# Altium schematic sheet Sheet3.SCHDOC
size B
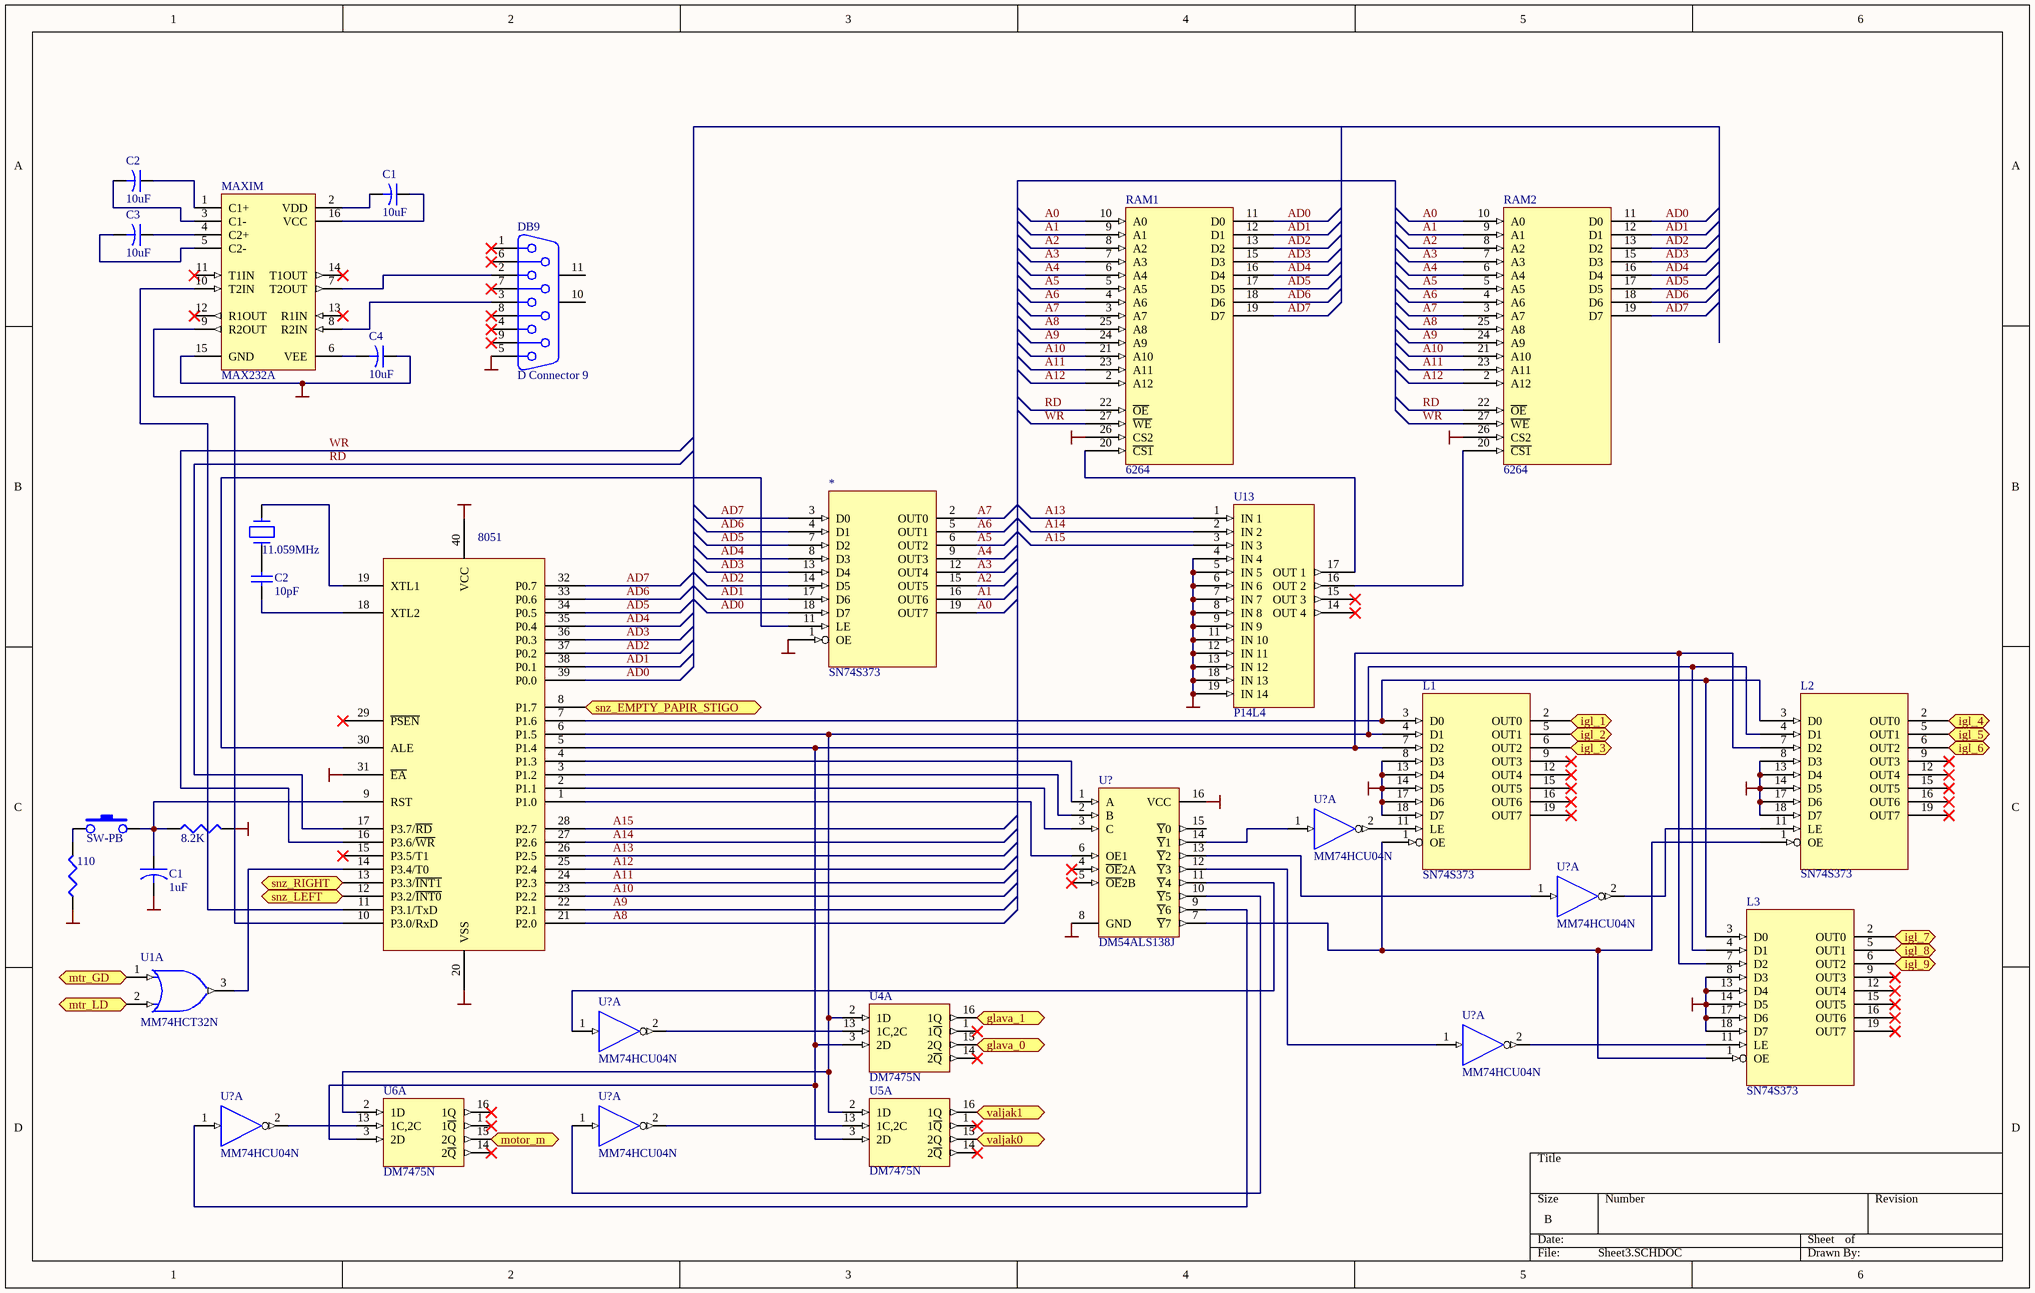
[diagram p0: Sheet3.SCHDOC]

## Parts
(Parts that share a designator on the sheet are numbered #1, #2 ... from top to bottom, then left to right.)
*  SN74S373
?#1  8051
?#2  11.059MHz
?#3  SW-PB
?#4  8.2K
?#5  110
C1#1  10uF  [CAPR5-4X5]
C1#2  1uF
C2#1  10uF  [CAPR5-4X5]
C2#2  value 10pF  [C3216-1206]
C3  10uF  [CAPR5-4X5]
C4  10uF  [CAPR5-4X5]
DB9  D Connector 9  [DSUB1.385-2H9]
L1  SN74S373
L2  SN74S373
L3  SN74S373
MAXIM  MAX232A  [SO-G16/G6.9]
RAM1  6264  [DIP28]
RAM2  6264  [DIP28]
U1  MM74HCT32N  [DIP-14/D19.7]  (part A of 4)
U4  DM7475N  [DIP-16]  (part A of 2)
U5  DM7475N  [DIP-16]  (part A of 2)
U6  DM7475N  [DIP-16]  (part A of 2)
U13  P14L4  [DIP20]
U?#1  DM54ALS138J  [DIP-16]
U?#2  MM74HCU04N  [DIP-14/D19.7]  (part A of 6)
U?#3  MM74HCU04N  [DIP-14/D19.7]  (part A of 6)
U?#4  MM74HCU04N  [DIP-14/D19.7]  (part A of 6)
U?#5  MM74HCU04N  [DIP-14/D19.7]  (part A of 6)
U?#6  MM74HCU04N  [DIP-14/D19.7]  (part A of 6)
U?#7  MM74HCU04N  [DIP-14/D19.7]  (part A of 6)

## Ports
glava_0, glava_1, igl_1, igl_2, igl_3, igl_4, igl_5, igl_6, igl_7, igl_8, igl_9, motor_m, mtr_GD, mtr_LD, snz_EMPTY_PAPIR_STIGO, snz_LEFT, snz_RIGHT, valjak0, valjak1

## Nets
GND: *.1(OE) ?#1.10(P3.0/RxD) ?#1.20(VSS) ?#4.2 C4.1 DB9.5 L1.8(D3) L1.13(D4) L1.14(D5) L1.17(D6) L1.18(D7) L2.8(D3) L2.13(D4) L2.14(D5) L2.17(D6) L2.18(D7) L3.8(D3) L3.13(D4) L3.14(D5) L3.17(D6) L3.18(D7) MAXIM.9(R2OUT) MAXIM.15(GND) RAM1.14(GND) RAM2.14(GND) U1.7(GND) U4.12(GND) U5.12(GND) U6.12(GND) U13.4(IN_4) U13.5(IN_5) U13.6(IN_6) U13.7(IN_7) U13.8(IN_8) U13.9(IN_9) U13.10(GND) U13.11(IN_10) U13.12(IN_11) U13.13(IN_12) U13.18(IN_13) U13.19(IN_14) U?#1.8(GND) U?#2.7(GND) U?#3.7(GND) U?#4.7(GND) U?#5.7(GND) U?#6.7(GND) U?#7.7(GND)
VCC: ?#1.31(~{EA}) ?#1.40(VCC) ?#5.1 C1#2.2 RAM1.26(CS2) RAM1.28(VCC) RAM2.26(CS2) RAM2.28(VCC) U1.14(VCC) U4.5(VCC) U5.5(VCC) U6.5(VCC) U13.20(VCC) U?#1.16(VCC) U?#2.14(VCC) U?#3.14(VCC) U?#4.14(VCC) U?#5.14(VCC) U?#6.14(VCC) U?#7.14(VCC)
A0: *.19(OUT7) RAM1.10(A0) RAM2.10(A0)
A1: *.16(OUT6) RAM1.9(A1) RAM2.9(A1)
A2: *.15(OUT5) RAM1.8(A2) RAM2.8(A2)
A3: *.12(OUT4) RAM1.7(A3) RAM2.7(A3)
A4: *.9(OUT3) RAM1.6(A4) RAM2.6(A4)
A5: *.6(OUT2) RAM1.5(A5) RAM2.5(A5)
A6: *.5(OUT1) RAM1.4(A6) RAM2.4(A6)
A7: *.2(OUT0) RAM1.3(A7) RAM2.3(A7)
A8: ?#1.21(P2.0) RAM1.25(A8) RAM2.25(A8)
A9: ?#1.22(P2.1) RAM1.24(A9) RAM2.24(A9)
A10: ?#1.23(P2.2) RAM1.21(A10) RAM2.21(A10)
A11: ?#1.24(P2.3) RAM1.23(A11) RAM2.23(A11)
A12: ?#1.25(P2.4) RAM1.2(A12) RAM2.2(A12)
A13: ?#1.26(P2.5) U13.1(IN_1)
A14: ?#1.27(P2.6) U13.2(IN_2)
A15: ?#1.28(P2.7) U13.3(IN_3)
AD0: *.18(D7) ?#1.39(P0.0) RAM1.11(D0) RAM2.11(D0)
AD1: *.17(D6) ?#1.38(P0.1) RAM1.12(D1) RAM2.12(D1)
AD2: *.14(D5) ?#1.37(P0.2) RAM1.13(D2) RAM2.13(D2)
AD3: *.13(D4) ?#1.36(P0.3) RAM1.15(D3) RAM2.15(D3)
AD4: *.8(D3) ?#1.35(P0.4) RAM1.16(D4) RAM2.16(D4)
AD5: *.7(D2) ?#1.34(P0.5) RAM1.17(D5) RAM2.17(D5)
AD6: *.4(D1) ?#1.33(P0.6) RAM1.18(D6) RAM2.18(D6)
AD7: *.3(D0) ?#1.32(P0.7) RAM1.19(D7) RAM2.19(D7)
glava_0: U4.15(2Q) ; port glava_0
glava_1: U4.16(1Q) ; port glava_1
igl_1: L1.2(OUT0) ; port igl_1
igl_2: L1.5(OUT1) ; port igl_2
igl_3: L1.6(OUT2) ; port igl_3
igl_4: L2.2(OUT0) ; port igl_4
igl_5: L2.5(OUT1) ; port igl_5
igl_6: L2.6(OUT2) ; port igl_6
igl_7: L3.2(OUT0) ; port igl_7
igl_8: L3.5(OUT1) ; port igl_8
igl_9: L3.6(OUT2) ; port igl_9
motor_m: U6.15(2Q) ; port motor_m
mtr_GD: U1.1(A) ; port mtr_GD
mtr_LD: U1.2(B) ; port mtr_LD
RD: ?#1.17(P3.7/~{RD}) RAM1.22(~{OE}) RAM2.22(~{OE})
snz_EMPTY_PAPIR_STIGO: ?#1.8(P1.7) ; port snz_EMPTY_PAPIR_STIGO
snz_LEFT: ?#1.12(P3.2/~{INT0}) ; port snz_LEFT
snz_RIGHT: ?#1.13(P3.3/~{INT1}) ; port snz_RIGHT
valjak0: U5.15(2Q) ; port valjak0
valjak1: U5.16(1Q) ; port valjak1
WR: ?#1.16(P3.6/~{WR}) RAM1.27(~{WE}) RAM2.27(~{WE})
Net*_11: *.11(LE) ?#1.30(ALE)
Net?#1_1: ?#1.1(P1.0) U?#1.6(OE1)
Net?#1_2: ?#1.2(P1.1) U?#1.3(C)
Net?#1_3: ?#1.3(P1.2) U?#1.2(B)
Net?#1_4: ?#1.4(P1.3) U?#1.1(A)
Net?#1_5: ?#1.5(P1.4) L1.7(D2) L2.7(D2) L3.7(D2) U4.3(2D) U5.3(2D) U6.3(2D)
Net?#1_6: ?#1.6(P1.5) L1.4(D1) L2.4(D1) L3.4(D1) U4.2(1D) U5.2(1D) U6.2(1D)
Net?#1_7: ?#1.7(P1.6) L1.3(D0) L2.3(D0) L3.3(D0)
Net?#1_9: ?#1.9(RST) ?#3.2 ?#4.1 C1#2.1
Net?#1_11: ?#1.11(P3.1/TxD) MAXIM.10(T2IN)
Net?#1_14: ?#1.14(P3.4/T0) U1.3(Y)
Net?#1_18: ?#1.18(XTL2) C2#2.2
Net?#1_19: ?#1.19(XTL1) ?#2.2
Net?#2_1: ?#2.1 C2#2.1
Net?#3_1: ?#3.1 ?#5.2
NetC1#1_1: C1#1.1 MAXIM.16(VCC)
NetC1#1_2: C1#1.2 MAXIM.2(VDD)
NetC2#1_1: C2#1.1 MAXIM.1(C1+)
NetC2#1_2: C2#1.2 MAXIM.3(C1-)
NetC3_1: C3.1 MAXIM.4(C2+)
NetC3_2: C3.2 MAXIM.5(C2-)
NetC4_2: C4.2 MAXIM.6(VEE)
NetDB9_2: DB9.2 MAXIM.7(T2OUT)
NetDB9_3: DB9.3 MAXIM.8(R2IN)
NetL1_1: L1.1(OE) L2.1(OE) L3.1(OE) U?#1.7(~{Y}7)
NetL1_11: L1.11(LE) U?#2.2(Y)
NetL2_11: L2.11(LE) U?#3.2(Y)
NetL3_11: L3.11(LE) U?#5.2(Y)
NetRAM1_20: RAM1.20(~{CS1}) U13.17(OUT_1)
NetRAM2_20: RAM2.20(~{CS1}) U13.16(OUT_2)
NetU4_13: U4.13(1C,2C) U?#4.2(Y)
NetU5_13: U5.13(1C,2C) U?#7.2(Y)
NetU6_13: U6.13(1C,2C) U?#6.2(Y)
NetU?#1_9: U?#1.9(~{Y}6) U?#6.1(A)
NetU?#1_10: U?#1.10(~{Y}5) U?#7.1(A)
NetU?#1_11: U?#1.11(~{Y}4) U?#4.1(A)
NetU?#1_12: U?#1.12(~{Y}3) U?#5.1(A)
NetU?#1_13: U?#1.13(~{Y}2) U?#3.1(A)
NetU?#1_14: U?#1.14(~{Y}1) U?#2.1(A)

Not connected (* = marked no-connect by the designer): * 10(GND) 20(VCC); ?#1 15(P3.5/T1)* 29(~{PSEN})*; DB9 1* 4* 6* 7* 8* 9* 10(MH1) 11(MH2); L1 9(OUT3)* 10(GND) 12(OUT4)* 15(OUT5)* 16(OUT6)* 19(OUT7)* 20(VCC); L2 9(OUT3)* 10(GND) 12(OUT4)* 15(OUT5)* 16(OUT6)* 19(OUT7)* 20(VCC); L3 9(OUT3)* 10(GND) 12(OUT4)* 15(OUT5)* 16(OUT6)* 19(OUT7)* 20(VCC); MAXIM 11(T1IN)* 12(R1OUT)* 13(R1IN)* 14(T1OUT)*; U4 1(1~{Q})* 14(2~{Q})*; U5 1(1~{Q})* 14(2~{Q})*; U6 1(1~{Q})* 14(2~{Q})* 16(1Q)*; U13 14(OUT_4)* 15(OUT_3)*; U?#1 4(~{OE}2A)* 5(~{OE}2B)* 15(~{Y}0)

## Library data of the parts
?#2 = CRYSTAL
?#4 ?#5 = RES1
C1#1 C2#1 C3 C4 = Cap2: Capacitor; Manufacturer: Generic Components; Class I: Passive
C1#2 = CAPACITOR
C2#2 = Cap Semi: Capacitor (Semiconductor SIM Model); Manufacturer: Generic Components; Class I: Passive
DB9 = D Connector 9: Receptacle Assembly, 9 Position, Right Angle; Manufacturer: Generic Components; Package Information: Latest Revision: O; Positions: 9
MAXIM = MAX232CWE: +5V Powered RS-232 Driver/Receiver; Manufacturer: Maxim; Class I: Communication; Class II: Transceiver
U1 = MM74HCT32N: Quad 2-Input OR Gate; Manufacturer: National Semiconductor; Class I: Logic
U4-U6 = DM7475N: Quad Latch; Manufacturer: National Semiconductor; Class I: Logic
U13 = P14L4: COMBINATORIAL LOGIC, WITH NO FEEDBACK 20-PIN PAL DEVICE
U?#1 = DM54ALS138J: 3-to-8-Line Decoder/Demultiplexer; Manufacturer: National Semiconductor; Class I: Logic
U?#2-U?#7 = MM74HCU04N: Hex Inverter; Manufacturer: National Semiconductor; Class I: Logic; Class II: Gate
